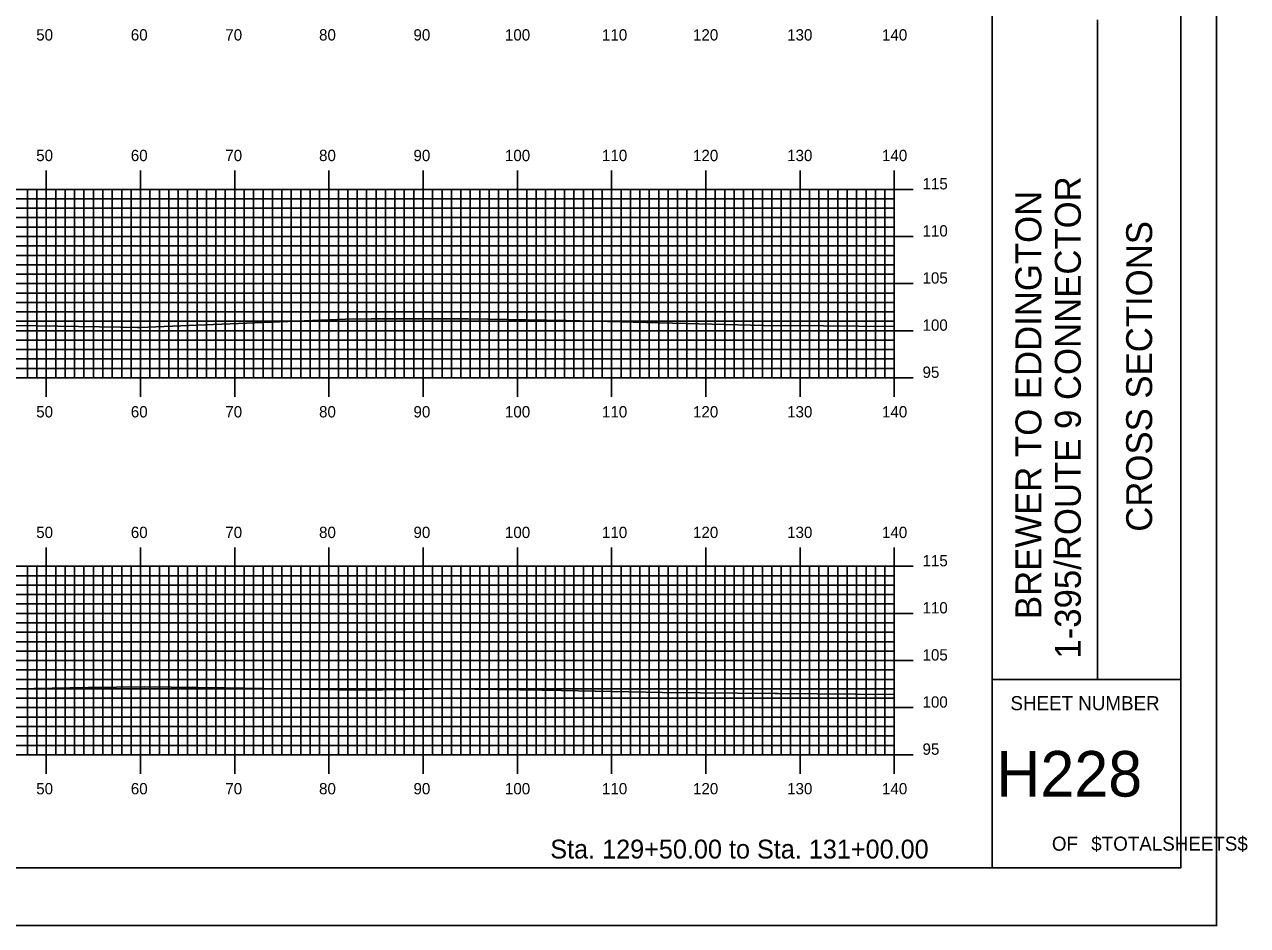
# Model space of a CAD drawing. Extents: x 1773990 to 1774333, y 442591 to 442811.
# Drawn here: x 1774203.3 to 1774333.2, y 442590.5 to 442686.2 of the extents above; entities that cross this region are included whole.
import ezdxf

# ---------------------------------------------------------------- set-up
doc = ezdxf.new("R2010")
doc.units = 0
for name, color, linetype in [('BORDER', 7, 'Continuous'), ('H_V ANNOTATION', 7, 'Continuous'), ('MAJOR', 7, 'Continuous'), ('MINOR', 7, 'Continuous'), ('PLOT BOUNDARY', 7, 'Continuous'), ('S_Roadway_Centerline', 7, 'Continuous')]:
    doc.layers.add(name, color=color, linetype=linetype)

msp = doc.modelspace()

# ---------------------------------------------------------------- linework, layer by layer
at = {"layer": 'BORDER'}
for p, q in [((1774306.06, 442596.67), (1774306.06, 442806.67)), ((1774317.24, 442616.67), (1774317.24, 442686.67)), ((1774306.06, 442616.67), (1774326.06, 442616.67))]:
    msp.add_line(p, q, dxfattribs=at)
msp.add_lwpolyline([(1774006.06, 442596.67), (1774326.06, 442596.67), (1774326.06, 442806.67), (1774006.06, 442806.67)], close=True, dxfattribs=at)
at = {"layer": 'MAJOR'}
for p, q in [((1774205.66, 442670.67), (1774205.66, 442668.67)), ((1774215.66, 442670.67), (1774215.66, 442668.67)), ((1774225.66, 442670.67), (1774225.66, 442668.67)), ((1774235.66, 442670.67), (1774235.66, 442668.67)), ((1774245.66, 442670.67), (1774245.66, 442668.67)), ((1774255.66, 442670.67), (1774255.66, 442668.67)), ((1774265.66, 442670.67), (1774265.66, 442668.67)), ((1774275.66, 442670.67), (1774275.66, 442668.67)), ((1774285.66, 442670.67), (1774285.66, 442668.67)), ((1774295.66, 442670.67), (1774295.66, 442668.67)), ((1774015.66, 442668.67), (1774295.66, 442668.67)), ((1774015.66, 442668.67), (1774295.66, 442668.67)), ((1774205.66, 442648.67), (1774205.66, 442668.67)), ((1774215.66, 442648.67), (1774215.66, 442668.67)), ((1774225.66, 442648.67), (1774225.66, 442668.67)), ((1774235.66, 442648.67), (1774235.66, 442668.67)), ((1774245.66, 442648.67), (1774245.66, 442668.67)), ((1774255.66, 442648.67), (1774255.66, 442668.67)), ((1774265.66, 442648.67), (1774265.66, 442668.67)), ((1774275.66, 442648.67), (1774275.66, 442668.67)), ((1774285.66, 442648.67), (1774285.66, 442668.67)), ((1774297.66, 442668.67), (1774293.65, 442668.67)), ((1774295.66, 442648.67), (1774295.66, 442668.67)), ((1774295.66, 442648.67), (1774295.66, 442668.67)), ((1774015.66, 442663.67), (1774295.66, 442663.67)), ((1774297.66, 442663.67), (1774293.65, 442663.67)), ((1774015.66, 442658.67), (1774295.66, 442658.67)), ((1774297.66, 442658.67), (1774293.65, 442658.67)), ((1774015.66, 442653.67), (1774295.66, 442653.67)), ((1774297.66, 442653.67), (1774293.65, 442653.67)), ((1774015.66, 442648.67), (1774295.66, 442648.67)), ((1774015.66, 442648.67), (1774295.66, 442648.67)), ((1774205.66, 442646.66), (1774205.66, 442648.67)), ((1774215.66, 442646.66), (1774215.66, 442648.67)), ((1774225.66, 442646.66), (1774225.66, 442648.67)), ((1774235.66, 442646.66), (1774235.66, 442648.67)), ((1774245.66, 442646.66), (1774245.66, 442648.67)), ((1774255.66, 442646.66), (1774255.66, 442648.67)), ((1774265.66, 442646.66), (1774265.66, 442648.67)), ((1774275.66, 442646.66), (1774275.66, 442648.67)), ((1774285.66, 442646.66), (1774285.66, 442648.67)), ((1774297.66, 442648.67), (1774293.65, 442648.67)), ((1774295.66, 442646.66), (1774295.66, 442648.67)), ((1774205.66, 442630.67), (1774205.66, 442628.67)), ((1774215.66, 442630.67), (1774215.66, 442628.67)), ((1774225.66, 442630.67), (1774225.66, 442628.67)), ((1774235.66, 442630.67), (1774235.66, 442628.67)), ((1774245.66, 442630.67), (1774245.66, 442628.67)), ((1774255.66, 442630.67), (1774255.66, 442628.67)), ((1774265.66, 442630.67), (1774265.66, 442628.67)), ((1774275.66, 442630.67), (1774275.66, 442628.67)), ((1774285.66, 442630.67), (1774285.66, 442628.67)), ((1774295.66, 442630.67), (1774295.66, 442628.67)), ((1774015.66, 442628.67), (1774295.66, 442628.67)), ((1774015.66, 442628.67), (1774295.66, 442628.67)), ((1774205.66, 442608.67), (1774205.66, 442628.67)), ((1774215.66, 442608.67), (1774215.66, 442628.67)), ((1774225.66, 442608.67), (1774225.66, 442628.67)), ((1774235.66, 442608.67), (1774235.66, 442628.67)), ((1774245.66, 442608.67), (1774245.66, 442628.67)), ((1774255.66, 442608.67), (1774255.66, 442628.67)), ((1774265.66, 442608.67), (1774265.66, 442628.67)), ((1774275.66, 442608.67), (1774275.66, 442628.67)), ((1774285.66, 442608.67), (1774285.66, 442628.67)), ((1774297.66, 442628.67), (1774293.65, 442628.67)), ((1774295.66, 442608.67), (1774295.66, 442628.67)), ((1774295.66, 442608.67), (1774295.66, 442628.67)), ((1774015.66, 442623.67), (1774295.66, 442623.67)), ((1774297.66, 442623.67), (1774293.65, 442623.67)), ((1774015.66, 442618.67), (1774295.66, 442618.67)), ((1774297.66, 442618.67), (1774293.65, 442618.67)), ((1774015.66, 442613.67), (1774295.66, 442613.67)), ((1774297.66, 442613.67), (1774293.65, 442613.67)), ((1774015.66, 442608.67), (1774295.66, 442608.67)), ((1774015.66, 442608.67), (1774295.66, 442608.67)), ((1774205.66, 442606.66), (1774205.66, 442608.67)), ((1774215.66, 442606.66), (1774215.66, 442608.67)), ((1774225.66, 442606.66), (1774225.66, 442608.67)), ((1774235.66, 442606.66), (1774235.66, 442608.67)), ((1774245.66, 442606.66), (1774245.66, 442608.67)), ((1774255.66, 442606.66), (1774255.66, 442608.67)), ((1774265.66, 442606.66), (1774265.66, 442608.67)), ((1774275.66, 442606.66), (1774275.66, 442608.67)), ((1774285.66, 442606.66), (1774285.66, 442608.67)), ((1774297.66, 442608.67), (1774293.65, 442608.67)), ((1774295.66, 442606.66), (1774295.66, 442608.67))]:
    msp.add_line(p, q, dxfattribs=at)
at = {"layer": 'MINOR'}
for p, q in [((1774015.66, 442667.67), (1774295.66, 442667.67)), ((1774203.66, 442648.67), (1774203.66, 442668.67)), ((1774204.66, 442648.67), (1774204.66, 442668.67)), ((1774206.66, 442648.67), (1774206.66, 442668.67)), ((1774207.66, 442648.67), (1774207.66, 442668.67)), ((1774208.66, 442648.67), (1774208.66, 442668.67)), ((1774209.66, 442648.67), (1774209.66, 442668.67)), ((1774210.66, 442648.67), (1774210.66, 442668.67)), ((1774211.66, 442648.67), (1774211.66, 442668.67)), ((1774212.66, 442648.67), (1774212.66, 442668.67)), ((1774213.66, 442648.67), (1774213.66, 442668.67)), ((1774214.66, 442648.67), (1774214.66, 442668.67)), ((1774216.66, 442648.67), (1774216.66, 442668.67)), ((1774217.66, 442648.67), (1774217.66, 442668.67)), ((1774218.66, 442648.67), (1774218.66, 442668.67)), ((1774219.66, 442648.67), (1774219.66, 442668.67)), ((1774220.66, 442648.67), (1774220.66, 442668.67)), ((1774221.66, 442648.67), (1774221.66, 442668.67)), ((1774222.66, 442648.67), (1774222.66, 442668.67)), ((1774223.66, 442648.67), (1774223.66, 442668.67)), ((1774224.66, 442648.67), (1774224.66, 442668.67)), ((1774226.66, 442648.67), (1774226.66, 442668.67)), ((1774227.66, 442648.67), (1774227.66, 442668.67)), ((1774228.66, 442648.67), (1774228.66, 442668.67)), ((1774229.66, 442648.67), (1774229.66, 442668.67)), ((1774230.66, 442648.67), (1774230.66, 442668.67)), ((1774231.66, 442648.67), (1774231.66, 442668.67)), ((1774232.66, 442648.67), (1774232.66, 442668.67)), ((1774233.66, 442648.67), (1774233.66, 442668.67)), ((1774234.66, 442648.67), (1774234.66, 442668.67)), ((1774236.66, 442648.67), (1774236.66, 442668.67)), ((1774237.66, 442648.67), (1774237.66, 442668.67)), ((1774238.66, 442648.67), (1774238.66, 442668.67)), ((1774239.66, 442648.67), (1774239.66, 442668.67)), ((1774240.66, 442648.67), (1774240.66, 442668.67)), ((1774241.66, 442648.67), (1774241.66, 442668.67)), ((1774242.66, 442648.67), (1774242.66, 442668.67)), ((1774243.66, 442648.67), (1774243.66, 442668.67)), ((1774244.66, 442648.67), (1774244.66, 442668.67)), ((1774246.66, 442648.67), (1774246.66, 442668.67)), ((1774247.66, 442648.67), (1774247.66, 442668.67)), ((1774248.66, 442648.67), (1774248.66, 442668.67)), ((1774249.66, 442648.67), (1774249.66, 442668.67)), ((1774250.66, 442648.67), (1774250.66, 442668.67)), ((1774251.66, 442648.67), (1774251.66, 442668.67)), ((1774252.66, 442648.67), (1774252.66, 442668.67)), ((1774253.66, 442648.67), (1774253.66, 442668.67)), ((1774254.66, 442648.67), (1774254.66, 442668.67)), ((1774256.66, 442648.67), (1774256.66, 442668.67)), ((1774257.66, 442648.67), (1774257.66, 442668.67)), ((1774258.66, 442648.67), (1774258.66, 442668.67)), ((1774259.66, 442648.67), (1774259.66, 442668.67)), ((1774260.66, 442648.67), (1774260.66, 442668.67)), ((1774261.66, 442648.67), (1774261.66, 442668.67)), ((1774262.66, 442648.67), (1774262.66, 442668.67)), ((1774263.66, 442648.67), (1774263.66, 442668.67)), ((1774264.66, 442648.67), (1774264.66, 442668.67)), ((1774266.66, 442648.67), (1774266.66, 442668.67)), ((1774267.66, 442648.67), (1774267.66, 442668.67)), ((1774268.66, 442648.67), (1774268.66, 442668.67)), ((1774269.66, 442648.67), (1774269.66, 442668.67)), ((1774270.66, 442648.67), (1774270.66, 442668.67)), ((1774271.66, 442648.67), (1774271.66, 442668.67)), ((1774272.66, 442648.67), (1774272.66, 442668.67)), ((1774273.66, 442648.67), (1774273.66, 442668.67)), ((1774274.66, 442648.67), (1774274.66, 442668.67)), ((1774276.66, 442648.67), (1774276.66, 442668.67)), ((1774277.66, 442648.67), (1774277.66, 442668.67)), ((1774278.66, 442648.67), (1774278.66, 442668.67)), ((1774279.66, 442648.67), (1774279.66, 442668.67)), ((1774280.66, 442648.67), (1774280.66, 442668.67)), ((1774281.66, 442648.67), (1774281.66, 442668.67)), ((1774282.66, 442648.67), (1774282.66, 442668.67)), ((1774283.66, 442648.67), (1774283.66, 442668.67)), ((1774284.66, 442648.67), (1774284.66, 442668.67)), ((1774286.66, 442648.67), (1774286.66, 442668.67)), ((1774287.66, 442648.67), (1774287.66, 442668.67)), ((1774288.66, 442648.67), (1774288.66, 442668.67)), ((1774289.66, 442648.67), (1774289.66, 442668.67)), ((1774290.66, 442648.67), (1774290.66, 442668.67)), ((1774291.66, 442648.67), (1774291.66, 442668.67)), ((1774292.66, 442648.67), (1774292.66, 442668.67)), ((1774295.66, 442667.67), (1774293.65, 442667.67)), ((1774293.66, 442648.67), (1774293.66, 442668.67)), ((1774294.66, 442648.67), (1774294.66, 442668.67)), ((1774015.66, 442666.67), (1774295.66, 442666.67)), ((1774295.66, 442666.67), (1774293.65, 442666.67)), ((1774015.66, 442665.67), (1774295.66, 442665.67)), ((1774295.66, 442665.67), (1774293.65, 442665.67)), ((1774015.66, 442664.67), (1774295.66, 442664.67)), ((1774295.66, 442664.67), (1774293.65, 442664.67)), ((1774015.66, 442662.67), (1774295.66, 442662.67)), ((1774295.66, 442662.67), (1774293.65, 442662.67)), ((1774015.66, 442661.67), (1774295.66, 442661.67)), ((1774295.66, 442661.67), (1774293.65, 442661.67)), ((1774015.66, 442660.67), (1774295.66, 442660.67)), ((1774295.66, 442660.67), (1774293.65, 442660.67)), ((1774015.66, 442659.67), (1774295.66, 442659.67)), ((1774295.66, 442659.67), (1774293.65, 442659.67)), ((1774015.66, 442657.67), (1774295.66, 442657.67)), ((1774295.66, 442657.67), (1774293.65, 442657.67)), ((1774015.66, 442656.67), (1774295.66, 442656.67)), ((1774295.66, 442656.67), (1774293.65, 442656.67)), ((1774015.66, 442655.67), (1774295.66, 442655.67)), ((1774015.66, 442654.67), (1774295.66, 442654.67)), ((1774295.66, 442655.67), (1774293.65, 442655.67)), ((1774295.66, 442654.67), (1774293.65, 442654.67)), ((1774015.66, 442652.67), (1774295.66, 442652.67)), ((1774295.66, 442652.67), (1774293.65, 442652.67)), ((1774015.66, 442651.67), (1774295.66, 442651.67)), ((1774015.66, 442650.67), (1774295.66, 442650.67)), ((1774295.66, 442651.67), (1774293.65, 442651.67)), ((1774295.66, 442650.67), (1774293.65, 442650.67)), ((1774015.66, 442649.67), (1774295.66, 442649.67)), ((1774295.66, 442649.67), (1774293.65, 442649.67)), ((1774203.66, 442608.67), (1774203.66, 442628.67)), ((1774204.66, 442608.67), (1774204.66, 442628.67)), ((1774206.66, 442608.67), (1774206.66, 442628.67)), ((1774207.66, 442608.67), (1774207.66, 442628.67)), ((1774208.66, 442608.67), (1774208.66, 442628.67)), ((1774209.66, 442608.67), (1774209.66, 442628.67)), ((1774210.66, 442608.67), (1774210.66, 442628.67)), ((1774211.66, 442608.67), (1774211.66, 442628.67)), ((1774212.66, 442608.67), (1774212.66, 442628.67)), ((1774213.66, 442608.67), (1774213.66, 442628.67)), ((1774214.66, 442608.67), (1774214.66, 442628.67)), ((1774216.66, 442608.67), (1774216.66, 442628.67)), ((1774217.66, 442608.67), (1774217.66, 442628.67)), ((1774218.66, 442608.67), (1774218.66, 442628.67)), ((1774219.66, 442608.67), (1774219.66, 442628.67)), ((1774220.66, 442608.67), (1774220.66, 442628.67)), ((1774221.66, 442608.67), (1774221.66, 442628.67)), ((1774222.66, 442608.67), (1774222.66, 442628.67)), ((1774223.66, 442608.67), (1774223.66, 442628.67)), ((1774224.66, 442608.67), (1774224.66, 442628.67)), ((1774226.66, 442608.67), (1774226.66, 442628.67)), ((1774227.66, 442608.67), (1774227.66, 442628.67)), ((1774228.66, 442608.67), (1774228.66, 442628.67)), ((1774229.66, 442608.67), (1774229.66, 442628.67)), ((1774230.66, 442608.67), (1774230.66, 442628.67)), ((1774231.66, 442608.67), (1774231.66, 442628.67)), ((1774232.66, 442608.67), (1774232.66, 442628.67)), ((1774233.66, 442608.67), (1774233.66, 442628.67)), ((1774234.66, 442608.67), (1774234.66, 442628.67)), ((1774236.66, 442608.67), (1774236.66, 442628.67)), ((1774237.66, 442608.67), (1774237.66, 442628.67)), ((1774238.66, 442608.67), (1774238.66, 442628.67)), ((1774239.66, 442608.67), (1774239.66, 442628.67)), ((1774240.66, 442608.67), (1774240.66, 442628.67)), ((1774241.66, 442608.67), (1774241.66, 442628.67)), ((1774242.66, 442608.67), (1774242.66, 442628.67)), ((1774243.66, 442608.67), (1774243.66, 442628.67)), ((1774244.66, 442608.67), (1774244.66, 442628.67)), ((1774246.66, 442608.67), (1774246.66, 442628.67)), ((1774247.66, 442608.67), (1774247.66, 442628.67)), ((1774248.66, 442608.67), (1774248.66, 442628.67)), ((1774249.66, 442608.67), (1774249.66, 442628.67)), ((1774250.66, 442608.67), (1774250.66, 442628.67)), ((1774251.66, 442608.67), (1774251.66, 442628.67)), ((1774252.66, 442608.67), (1774252.66, 442628.67)), ((1774253.66, 442608.67), (1774253.66, 442628.67)), ((1774254.66, 442608.67), (1774254.66, 442628.67)), ((1774256.66, 442608.67), (1774256.66, 442628.67)), ((1774257.66, 442608.67), (1774257.66, 442628.67)), ((1774258.66, 442608.67), (1774258.66, 442628.67)), ((1774259.66, 442608.67), (1774259.66, 442628.67)), ((1774260.66, 442608.67), (1774260.66, 442628.67)), ((1774261.66, 442608.67), (1774261.66, 442628.67)), ((1774262.66, 442608.67), (1774262.66, 442628.67)), ((1774263.66, 442608.67), (1774263.66, 442628.67)), ((1774264.66, 442608.67), (1774264.66, 442628.67)), ((1774266.66, 442608.67), (1774266.66, 442628.67)), ((1774267.66, 442608.67), (1774267.66, 442628.67)), ((1774268.66, 442608.67), (1774268.66, 442628.67)), ((1774269.66, 442608.67), (1774269.66, 442628.67)), ((1774270.66, 442608.67), (1774270.66, 442628.67)), ((1774271.66, 442608.67), (1774271.66, 442628.67)), ((1774272.66, 442608.67), (1774272.66, 442628.67)), ((1774273.66, 442608.67), (1774273.66, 442628.67)), ((1774274.66, 442608.67), (1774274.66, 442628.67)), ((1774276.66, 442608.67), (1774276.66, 442628.67)), ((1774277.66, 442608.67), (1774277.66, 442628.67)), ((1774278.66, 442608.67), (1774278.66, 442628.67)), ((1774279.66, 442608.67), (1774279.66, 442628.67)), ((1774280.66, 442608.67), (1774280.66, 442628.67)), ((1774281.66, 442608.67), (1774281.66, 442628.67)), ((1774282.66, 442608.67), (1774282.66, 442628.67)), ((1774283.66, 442608.67), (1774283.66, 442628.67)), ((1774284.66, 442608.67), (1774284.66, 442628.67)), ((1774286.66, 442608.67), (1774286.66, 442628.67)), ((1774287.66, 442608.67), (1774287.66, 442628.67)), ((1774288.66, 442608.67), (1774288.66, 442628.67)), ((1774289.66, 442608.67), (1774289.66, 442628.67)), ((1774290.66, 442608.67), (1774290.66, 442628.67)), ((1774291.66, 442608.67), (1774291.66, 442628.67)), ((1774292.66, 442608.67), (1774292.66, 442628.67)), ((1774293.66, 442608.67), (1774293.66, 442628.67)), ((1774294.66, 442608.67), (1774294.66, 442628.67)), ((1774015.66, 442627.67), (1774295.66, 442627.67)), ((1774295.66, 442627.67), (1774293.65, 442627.67)), ((1774015.66, 442626.67), (1774295.66, 442626.67)), ((1774295.66, 442626.67), (1774293.65, 442626.67)), ((1774015.66, 442625.67), (1774295.66, 442625.67)), ((1774015.66, 442624.67), (1774295.66, 442624.67)), ((1774295.66, 442625.67), (1774293.65, 442625.67)), ((1774295.66, 442624.67), (1774293.65, 442624.67)), ((1774015.66, 442622.67), (1774295.66, 442622.67)), ((1774295.66, 442622.67), (1774293.65, 442622.67)), ((1774015.66, 442621.67), (1774295.66, 442621.67)), ((1774295.66, 442621.67), (1774293.65, 442621.67)), ((1774015.66, 442620.67), (1774295.66, 442620.67)), ((1774015.66, 442619.67), (1774295.66, 442619.67)), ((1774295.66, 442620.67), (1774293.65, 442620.67)), ((1774295.66, 442619.67), (1774293.65, 442619.67)), ((1774015.66, 442617.67), (1774295.66, 442617.67)), ((1774295.66, 442617.67), (1774293.65, 442617.67)), ((1774015.66, 442616.67), (1774295.66, 442616.67)), ((1774015.66, 442615.67), (1774295.66, 442615.67)), ((1774295.66, 442616.67), (1774293.65, 442616.67)), ((1774295.66, 442615.67), (1774293.65, 442615.67)), ((1774015.66, 442614.67), (1774295.66, 442614.67)), ((1774295.66, 442614.67), (1774293.65, 442614.67)), ((1774015.66, 442612.67), (1774295.66, 442612.67)), ((1774015.66, 442611.67), (1774295.66, 442611.67)), ((1774295.66, 442612.67), (1774293.65, 442612.67)), ((1774295.66, 442611.67), (1774293.65, 442611.67)), ((1774015.66, 442610.67), (1774295.66, 442610.67)), ((1774295.66, 442610.67), (1774293.65, 442610.67)), ((1774015.66, 442609.67), (1774295.66, 442609.67)), ((1774295.66, 442609.67), (1774293.65, 442609.67))]:
    msp.add_line(p, q, dxfattribs=at)
at = {"layer": 'PLOT BOUNDARY'}
msp.add_lwpolyline([(1773989.87, 442590.55), (1774329.87, 442590.55), (1774329.87, 442810.55), (1773989.87, 442810.55)], close=True, dxfattribs=at)
at = {"layer": 'S_Roadway_Centerline'}
for points in [[(1774193.51, 442654.38), (1774213.52, 442654.06), (1774215.34, 442654.03), (1774215.45, 442654.03), (1774215.56, 442654.03), (1774237.41, 442654.91), (1774240.15, 442654.94), (1774250.45, 442654.92), (1774260.85, 442654.76), (1774263.83, 442654.69), (1774281.81, 442654.23), (1774288.15, 442654.2), (1774295.66, 442654.13)], [(1774194.73, 442615.52), (1774210.12, 442615.81), (1774216.12, 442615.89), (1774224.55, 442615.79), (1774238.87, 442615.52), (1774248.78, 442615.66), (1774258.3, 442615.51), (1774260.35, 442615.48), (1774271.07, 442615.26), (1774283.03, 442615.18), (1774283.19, 442615.17), (1774283.36, 442615.17), (1774295.66, 442615.06)]]:
    msp.add_lwpolyline(points, dxfattribs=at)

# ---------------------------------------------------------------- texts
at = {"layer": 'BORDER'}
for s, p in [('1-395/ROUTE 9 CONNECTOR', (1774315.46, 442618.87)), ('BREWER TO EDDINGTON', (1774311.28, 442623.07)), ('CROSS SECTIONS', (1774323.03, 442632.34))]:
    msp.add_text(s, height=2.7557, rotation=90, dxfattribs=at).set_placement(p)
for s, height, p in [('SHEET NUMBER', 1.4905, (1774307.99, 442613.4)), ('H228', 4.839, (1774306.5, 442604.23)), ('OF', 1.491, (1774312.39, 442598.49)), ('$TOTALSHEETS$', 1.4905, (1774316.57, 442598.49))]:
    msp.add_text(s, height=height, dxfattribs=at).set_placement(p)
at = {"layer": 'H_V ANNOTATION'}
for s, height, p in [('50', 1.2, (1774204.59, 442684.47)), ('60', 1.2, (1774214.63, 442684.47)), ('70', 1.2, (1774224.66, 442684.47)), ('80', 1.2, (1774234.61, 442684.47)), ('90', 1.2, (1774244.63, 442684.47)), ('100', 1.2, (1774254.34, 442684.47)), ('110', 1.2, (1774264.64, 442684.47)), ('120', 1.2, (1774274.3, 442684.47)), ('130', 1.2, (1774284.29, 442684.47)), ('140', 1.2, (1774294.36, 442684.47)), ('50', 1.2, (1774204.59, 442671.67)), ('60', 1.2, (1774214.63, 442671.67)), ('70', 1.2, (1774224.66, 442671.67)), ('80', 1.2, (1774234.61, 442671.67)), ('90', 1.2, (1774244.63, 442671.67)), ('100', 1.2, (1774254.34, 442671.67)), ('110', 1.2, (1774264.64, 442671.67)), ('120', 1.2, (1774274.3, 442671.67)), ('130', 1.2, (1774284.29, 442671.67)), ('140', 1.2, (1774294.36, 442671.67)), ('115', 1.2, (1774298.66, 442668.67)), ('110', 1.2, (1774298.66, 442663.67)), ('105', 1.2, (1774298.66, 442658.67)), ('100', 1.2, (1774298.66, 442653.67)), ('95', 1.2, (1774298.66, 442648.67)), ('50', 1.2, (1774204.59, 442644.47)), ('60', 1.2, (1774214.63, 442644.47)), ('70', 1.2, (1774224.66, 442644.47)), ('80', 1.2, (1774234.61, 442644.47)), ('90', 1.2, (1774244.63, 442644.47)), ('100', 1.2, (1774254.34, 442644.47)), ('110', 1.2, (1774264.64, 442644.47)), ('120', 1.2, (1774274.3, 442644.47)), ('130', 1.2, (1774284.29, 442644.47)), ('140', 1.2, (1774294.36, 442644.47)), ('50', 1.2, (1774204.59, 442631.67)), ('60', 1.2, (1774214.63, 442631.67)), ('70', 1.2, (1774224.66, 442631.67)), ('80', 1.2, (1774234.61, 442631.67)), ('90', 1.2, (1774244.63, 442631.67)), ('100', 1.2, (1774254.34, 442631.67)), ('110', 1.2, (1774264.64, 442631.67)), ('120', 1.2, (1774274.3, 442631.67)), ('130', 1.2, (1774284.29, 442631.67)), ('140', 1.2, (1774294.36, 442631.67)), ('115', 1.2, (1774298.66, 442628.67)), ('110', 1.2, (1774298.66, 442623.67)), ('105', 1.2, (1774298.66, 442618.67)), ('100', 1.2, (1774298.66, 442613.67)), ('95', 1.2, (1774298.66, 442608.67)), ('50', 1.2, (1774204.59, 442604.47)), ('60', 1.2, (1774214.63, 442604.47)), ('70', 1.2, (1774224.66, 442604.47)), ('80', 1.2, (1774234.61, 442604.47)), ('90', 1.2, (1774244.63, 442604.47)), ('100', 1.2, (1774254.34, 442604.47)), ('110', 1.2, (1774264.64, 442604.47)), ('120', 1.2, (1774274.3, 442604.47)), ('130', 1.2, (1774284.29, 442604.47)), ('140', 1.2, (1774294.36, 442604.47)), ('Sta. 129+50.00 to Sta. 131+00.00', 2.0004, (1774259.15, 442597.66))]:
    msp.add_text(s, height=height, dxfattribs=at).set_placement(p)

doc.saveas('drawing.dxf')
